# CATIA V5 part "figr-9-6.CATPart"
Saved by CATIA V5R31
Part number: Part2
Bounding box of the stored display mesh (mm): x -75 to 75, y -75 to 96.278, z -26.878 to 0
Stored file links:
  D:\PROJECTS\Project 2021\US EDITION\CATIA V5 6R 2021\Resources\Part Files\c09_catia_v5_6r2021_prt\c09_catia_v5_6r2021_prt\figr-9-6.CATPart
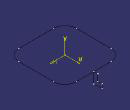
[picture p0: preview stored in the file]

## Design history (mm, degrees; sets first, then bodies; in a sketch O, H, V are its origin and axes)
Body1 (main body)
  Sketch1 on xy-plane, origin (0, 0, 0), H (1, 0, 0), V (0, 1, 0)
    point P1 (-75, 75)
    line L1 (-45, 75) -> (45, 75)
    line L2 (75, 45) -> (75, -45)
    line L3 (45, -75) -> (-45, -75)
    line L4 (-75, -45) -> (-75, 45)
    point P2 (75, 75)
    point P3 (75, -75)
    point P4 (-75, -75)
    axis line L5 (75, -75) -> (-75, 75)
    arc A1 centre (45, -45) radius 30 from (75, -45) to (45, -75) cw
    arc A2 centre (45, 45) radius 30 from (45, 75) to (75, 45) cw
    arc A3 centre (-45, 45) radius 30 from (-45, 75) to (-75, 45) ccw
    arc A4 centre (-45, -45) radius 30 from (-45, -75) to (-75, -45) cw
    distance P2 P3 = 150
    distance P3 P4 = 150
    radius A1 = 30
    radius A2 = 30
    radius A3 = 30
    radius A4 = 30
    horizontal: L1 H, L3 H
    vertical: L2 V, L4 V
    midpoint: O L5
    coincidence: L2 P3, L3 P3, L1 P2, L2 P2, L1 P1, L4 P1, L3 P4, L4 P4
    tangency: A1 L2, A1 L3, A2 L1, A2 L2, A3 L1, A3 L4, A4 L3, A4 L4
  Sketch2 on yz-plane, origin (0, 0, 0), H (0, 1, 0), V (0, 0, 1)
    point P1 (85, 0)
    line L1 (85, 0) -> (85, -16.8782)
    line L2 (85, -16.8782) -> (96.2781, -16.8782)
    line L3 (96.2781, -16.8782) -> (96.2781, -26.8782)
    line L4 (96.2781, -26.8782) -> (75, -26.8782)
    line L5 (75, -26.8782) -> (75, 0)
    point P6 (75, 0)
    line L6 (75, 0) -> (85, 0)
    reference projected point E1 (75, 0) from edge of Sketch1
    length L3 = 10
    length L6 = 10
    coincidence: P1 H, P6 H, P6 E1
    vertical: L1 V, L3 V, L5 V
    horizontal: L2 H, L4 H, L6 H
  Rib1: profile Sketch2, centre curve Sketch1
